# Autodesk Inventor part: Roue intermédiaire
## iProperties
Created: 2002-05
Part Number: Roue intermédiaire
Material: Par défaut
Document SubType Name: Modélisation
Designer: Flavien MARTY
Control State: 0
Master: False
Checked Out: False
Shininess: 20.0
Length Units: 11269
Angle Units: 11279
Time Units: 11290
Mass Units: 11283
Length Display Precision: 3
Angle Display Precision: 2
Compacted: True
Density: 0.0
Volumn: 0.0
Area: 0.0
PropertySet Name: Model Information
Author: Flavien MARTY
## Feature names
1. Extrusion1
2. Extrusion2
3. Perçage1 [Hole]
4. Extrusion3
